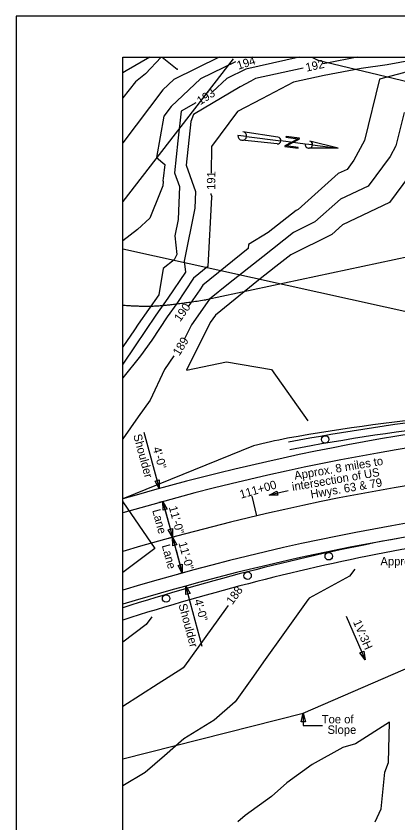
# Model space of a CAD drawing. Extents: x 1385284 to 1385995, y 1975154 to 1975620.
# Drawn here: x 1385283.8 to 1385397.4, y 1975379.9 to 1975619.6 of the extents above; entities that cross this region are included whole.
import ezdxf

# ---------------------------------------------------------------- set-up
doc = ezdxf.new("R2010")
doc.units = 0
for name, color, linetype in [('1', 7, 'Continuous'), ('Default', 7, 'Continuous'), ('DTM CONTOURS_MAJOR', 7, 'Continuous'), ('DTM_CONTOURS_MINOR', 7, 'Continuous'), ('Level 1', 7, 'Continuous'), ('R_Guardrail', 7, 'Continuous'), ('R_Horz Alg', 7, 'Continuous'), ('R_Horz Alg Annot', 7, 'Continuous'), ('R_Horz Alg Stationing', 7, 'Continuous'), ('R_Proposed Const Limits', 7, 'Continuous'), ('R_Proposed Road', 7, 'Continuous'), ('R_Shld', 7, 'Continuous'), ('S_CROSS_DRAIN', 7, 'Continuous'), ('S_DRG_PT_SYM', 7, 'Continuous'), ('S_SHOULDER', 7, 'Continuous'), ('S_UTL_PT_SYM', 7, 'Continuous'), ('S_WATER_UTILITIES', 7, 'Continuous')]:
    doc.layers.add(name, color=color, linetype=linetype)

msp = doc.modelspace()

# ---------------------------------------------------------------- linework, layer by layer
at = {"layer": '1'}
msp.add_line((1385315.54, 1975607.41), (1385982.69, 1975607.41), dxfattribs=at)
for points in [[(1385994.75, 1975619.62), (1385283.84, 1975619.62), (1385283.84, 1975153.74), (1385994.75, 1975153.74)], [(1385315.54, 1975165.95), (1385315.54, 1975607.41), (1385810.69, 1975607.41), (1385810.69, 1975586.48), (1385892.57, 1975586.48), (1385892.57, 1975580.3), (1385982.69, 1975580.3), (1385982.69, 1975165.95)]]:
    msp.add_lwpolyline(points, close=True, dxfattribs=at)
at = {"layer": 'Default'}
for p, q in [((1385321.87, 1975496.01), (1385326.44, 1975479.22)), ((1385325.23, 1975478.89), (1385325.23, 1975478.89)), ((1385364.76, 1975478.59), (1385359.11, 1975477.29)), ((1385328.05, 1975475.52), (1385326.28, 1975475.04)), ((1385327.49, 1975475.36), (1385330.37, 1975464.75)), ((1385329.32, 1975468.61), (1385327.49, 1975475.36)), ((1385326.28, 1975475.03), (1385326.28, 1975475.03)), ((1385330.94, 1975464.9), (1385329.17, 1975464.42)), ((1385330.37, 1975464.75), (1385333.26, 1975454.13)), ((1385331.42, 1975460.89), (1385333.26, 1975454.13)), ((1385333.82, 1975454.29), (1385332.05, 1975453.81)), ((1385332.05, 1975453.8), (1385332.05, 1975453.8)), ((1385333.1, 1975449.94), (1385333.1, 1975449.94)), ((1385339.2, 1975432.28), (1385334.31, 1975450.27)), ((1385382.05, 1975441.26), (1385387.65, 1975428.32)), ((1385369.26, 1975412.44), (1385369.26, 1975408.85)), ((1385369.26, 1975408.85), (1385374.94, 1975408.85))]:
    msp.add_line(p, q, dxfattribs=at)
for points in [[(1385326.38, 1975481.8), (1385326.44, 1975479.22), (1385325.18, 1975481.47)], [(1385361.69, 1975477.24), (1385359.11, 1975477.29), (1385361.41, 1975478.46)], [(1385327.54, 1975472.79), (1385327.49, 1975475.36), (1385328.75, 1975473.12)], [(1385327.54, 1975472.78), (1385327.49, 1975475.36), (1385328.75, 1975473.11)], [(1385330.32, 1975467.33), (1385330.37, 1975464.75), (1385329.11, 1975467)], [(1385330.42, 1975462.17), (1385330.37, 1975464.75), (1385331.63, 1975462.5)], [(1385333.21, 1975456.71), (1385333.26, 1975454.13), (1385332, 1975456.38)], [(1385333.21, 1975456.71), (1385333.26, 1975454.13), (1385332, 1975456.38)], [(1385334.36, 1975447.7), (1385334.31, 1975450.27), (1385335.57, 1975448.02)], [(1385387.23, 1975430.86), (1385387.65, 1975428.32), (1385386.08, 1975430.36)], [(1385368.63, 1975409.94), (1385369.26, 1975412.44), (1385369.88, 1975409.94)]]:
    msp.add_lwpolyline(points, close=True, dxfattribs=at)
at = {"layer": 'DTM CONTOURS_MAJOR'}
for points in [[(1385344.28, 1975607.41), (1385330.72, 1975600.78), (1385327.45, 1975597.68), (1385315.54, 1975581.97)], [(1385399.62, 1975602.92), (1385399.04, 1975602.82), (1385391.96, 1975600.88), (1385387.45, 1975582.67), (1385384.31, 1975576.79), (1385382.28, 1975574.04), (1385379.69, 1975572.81), (1385367.75, 1975562.2), (1385367.14, 1975561.9), (1385358.79, 1975555.31), (1385352.95, 1975551.79), (1385352.89, 1975550.54), (1385339.43, 1975539.66), (1385338.49, 1975538.24), (1385335.03, 1975533.36)], [(1385315.54, 1975475.27), (1385325.14, 1975461.45), (1385315.54, 1975454.26)]]:
    msp.add_lwpolyline(points, dxfattribs=at)
at = {"layer": 'DTM_CONTOURS_MINOR'}
for points in [[(1385327.01, 1975607.41), (1385322.31, 1975602.51), (1385319.36, 1975600.08), (1385315.54, 1975595.3)], [(1385368.04, 1975607.41), (1385352.21, 1975603.89), (1385346.56, 1975601.12), (1385342.3, 1975597.1)], [(1385385.31, 1975607.41), (1385376.24, 1975605.69), (1385375.12, 1975605.45)], [(1385349.07, 1975606.05), (1385338.64, 1975600.95), (1385330.01, 1975592.78), (1385327.83, 1975589.91), (1385325.56, 1975577.58), (1385328.04, 1975575.57), (1385327.55, 1975571.35), (1385327.49, 1975570.73), (1385327.58, 1975570.47), (1385327.53, 1975569.17), (1385326.67, 1975567.25), (1385323.63, 1975559.56), (1385319.95, 1975556.23), (1385315.54, 1975552.86)], [(1385514.59, 1975561.54), (1385512.54, 1975562.62), (1385501.11, 1975567.56), (1385496.85, 1975570), (1385485.37, 1975578.7), (1385479.84, 1975581.7), (1385469.1, 1975589.65), (1385457.89, 1975594.57), (1385449.84, 1975598.03), (1385440.13, 1975602.29), (1385428.54, 1975605.71), (1385423.05, 1975606.12), (1385417.26, 1975606.55), (1385404.45, 1975607), (1385394.25, 1975605.12), (1385386.47, 1975604.03), (1385375.43, 1975601.95), (1385366.35, 1975599.96), (1385356.91, 1975595.01), (1385349.74, 1975591.25), (1385341.99, 1975580.91), (1385341.88, 1975572.91)], [(1385369.26, 1975604.16), (1385355.09, 1975601.06), (1385353.62, 1975600.29), (1385350.48, 1975598.64), (1385336.6, 1975590.39), (1385335.78, 1975588.28), (1385334.46, 1975575.29), (1385337.21, 1975567.51), (1385337.02, 1975562.57), (1385333.86, 1975546.8), (1385334.18, 1975543.53), (1385328.93, 1975535.79), (1385325.43, 1975530.76), (1385319.28, 1975521.64), (1385315.54, 1975516.24)], [(1385337.27, 1975593.88), (1385332.96, 1975591.37), (1385331.95, 1975582.54), (1385330.97, 1975573.01), (1385332.4, 1975568.99), (1385332.02, 1975559.15), (1385331.06, 1975554.36), (1385331.61, 1975548.75), (1385330.89, 1975547.15), (1385327.6, 1975544.63), (1385326.26, 1975536.84), (1385320.18, 1975528.09), (1385319.01, 1975526.36), (1385315.54, 1975521.35)], [(1385399.23, 1975591.02), (1385396.78, 1975581.11), (1385395.07, 1975577.92), (1385388.6, 1975569.12), (1385380.31, 1975565.21), (1385372.74, 1975558.48), (1385366.36, 1975555.31), (1385357.23, 1975548.12), (1385346.99, 1975540.04), (1385341.41, 1975535.54), (1385335.97, 1975527.87), (1385333.9, 1975523.73)], [(1385402.83, 1975574.97), (1385394.91, 1975564.2), (1385380.94, 1975557.61), (1385377.74, 1975554.77), (1385365.57, 1975548.73), (1385361.06, 1975545.17), (1385355.99, 1975541.17), (1385343.15, 1975530.79), (1385341.61, 1975528.62), (1385334.49, 1975514.44), (1385346.45, 1975516.91), (1385359.8, 1975514.64), (1385370.64, 1975499.32)], [(1385341.8, 1975566.91), (1385341.79, 1975566.68), (1385342.03, 1975566.02), (1385342.03, 1975566), (1385341.99, 1975565.82), (1385340.91, 1975545.21), (1385336.65, 1975541.76), (1385331.68, 1975534.26), (1385328.81, 1975530.22), (1385324.2, 1975523.32), (1385320.87, 1975518.63), (1385315.54, 1975512.1)], [(1385330.78, 1975518.63), (1385327.94, 1975514.62), (1385323.7, 1975505.5), (1385320.15, 1975500.5), (1385315.54, 1975494)], [(1385384.61, 1975455.29), (1385383.06, 1975453.21), (1385371, 1975446.69), (1385370.71, 1975446.29), (1385370.59, 1975446.12), (1385363.19, 1975435.73), (1385357.96, 1975428.4), (1385353.91, 1975422.75), (1385348.97, 1975415.84), (1385342.72, 1975410.39), (1385333.74, 1975404.82), (1385328, 1975399.83), (1385322.27, 1975394.83), (1385315.54, 1975390.88)], [(1385346.83, 1975444.43), (1385346.81, 1975444.4), (1385346.1, 1975443.41), (1385333.91, 1975426.45), (1385333.58, 1975425.99), (1385333.17, 1975425.63), (1385326.07, 1975421.23), (1385315.54, 1975414.45)], [(1385324.2, 1975441.14), (1385322.56, 1975438.81), (1385315.54, 1975433.55)], [(1385390.67, 1975380.2), (1385392.4, 1975384.09), (1385393.51, 1975394.98), (1385394.58, 1975397.83), (1385394.96, 1975409.79), (1385384.78, 1975403.37), (1385381.07, 1975402.27), (1385371.89, 1975397.26), (1385364.39, 1975391.78), (1385359.79, 1975387.75), (1385352.01, 1975382.09), (1385349.84, 1975380.2)]]:
    msp.add_lwpolyline(points, dxfattribs=at)
at = {"layer": 'Level 1'}
for p, q in [((1385352.4, 1975583.84), (1385349.83, 1975584.17)), ((1385349.83, 1975584.17), (1385349.83, 1975584.17)), ((1385361.72, 1975583.64), (1385351.32, 1975585.28)), ((1385352.4, 1975583.84), (1385362.57, 1975582.54)), ((1385364.14, 1975583.86), (1385364.11, 1975583.61)), ((1385368.07, 1975583.1), (1385368.11, 1975583.35)), ((1385361.47, 1975581.68), (1385350.99, 1975582.72)), ((1385369.84, 1975581.61), (1385362.57, 1975582.54)), ((1385363.79, 1975581.11), (1385363.75, 1975580.86)), ((1385371.98, 1975581.33), (1385369.84, 1975581.61)), ((1385369.84, 1975581.61), (1385369.84, 1975581.59)), ((1385379.66, 1975580.35), (1385371.17, 1975582.5)), ((1385371.98, 1975581.33), (1385379.66, 1975580.35)), ((1385367.72, 1975580.35), (1385367.75, 1975580.6)), ((1385379.66, 1975580.35), (1385370.9, 1975580.38))]:
    msp.add_line(p, q, dxfattribs=at)
for points in [[(1385367.71, 1975583.15), (1385363.79, 1975581.11)], [(1385364.11, 1975583.61), (1385367.71, 1975583.15)], [(1385368.11, 1975583.35), (1385364.14, 1975583.86)], [(1385364.15, 1975581.07), (1385368.07, 1975583.1)], [(1385363.75, 1975580.86), (1385367.72, 1975580.35)], [(1385367.75, 1975580.6), (1385364.15, 1975581.07)]]:
    msp.add_lwpolyline(points, dxfattribs=at)
for centre, radius, start, end in [((1385351.11, 1975584), 1.29, 172.7064, 352.7064), ((1385351.11, 1975584), 1.29, 352.7064, 81.0414), ((1385361.6, 1975582.66), 0.984, 352.7034, 82.777), ((1385361.6, 1975582.66), 0.984, 262.777, 352.7034), ((1385370.91, 1975581.46), 1.08, 173.0609, 353.2831), ((1385370.91, 1975581.46), 1.08, 353.2831, 75.7678)]:
    msp.add_arc(centre, radius, start, end, dxfattribs=at)
at = {"layer": 'R_Guardrail'}
for centre in [(1385375.79, 1975493.83), (1385376.84, 1975459.11), (1385352.69, 1975453.34), (1385328.45, 1975446.56)]:
    msp.add_circle(centre, 1.11, dxfattribs=at)
for centre, radius, start, end in [((1385496.71, 1974793.55), 711.77, 96.54062, 100.67501), ((1385496.71, 1974793.55), 709.49, 96.54062, 100.67501), ((1385515.91, 1974795.32), 679.49, 96.60918, 100.21868), ((1385522.21, 1974796.51), 679.47, 100.75858, 107.70744)]:
    msp.add_arc(centre, radius, start, end, dxfattribs=at)
at = {"layer": 'R_Horz Alg'}
msp.add_arc((1385514.36, 1974795.07), 694.49, 77.49826, 106.63511, dxfattribs=at)
at = {"layer": 'R_Horz Alg Annot'}
for p, q in [((1385348.44, 1975606.95), (1385315.54, 1975564.49)), ((1385315.54, 1975550.51), (1385664.69, 1975473.09))]:
    msp.add_line(p, q, dxfattribs=at)
at = {"layer": 'R_Horz Alg Stationing'}
msp.add_line((1385355.46, 1975471.14), (1385354.09, 1975476.98), dxfattribs=at)
at = {"layer": 'R_Proposed Const Limits'}
for points in [[(1385461.53, 1975561.1), (1385340.37, 1975535.35)], [(1385315.54, 1975398.93), (1385369.26, 1975412.44), (1385438.34, 1975442.35)]]:
    msp.add_lwpolyline(points, dxfattribs=at)
msp.add_open_spline([(1385315.54, 1975533.74), (1385321.69, 1975533.28), (1385329.85, 1975533.76), (1385340.37, 1975535.35)], degree=2, dxfattribs=at)
at = {"layer": 'R_Proposed Road'}
for radius, end in [(705.49, 106.36838), (683.49, 106.91082)]:
    msp.add_arc((1385514.36, 1974795.07), radius, 77.49826, end, dxfattribs=at)
at = {"layer": 'R_Shld'}
msp.add_line((1385354.45, 1975491.95), (1385315.54, 1975476.17), dxfattribs=at)
for centre, radius, start, end in [((1385514.36, 1974795.07), 709.49, 93.55435, 106.27353), ((1385487.08, 1974789.91), 714.86, 95.74275, 99.87127), ((1385514.67, 1974793.6), 716.49, 102.09645, 102.92145), ((1385514.36, 1974795.07), 679.49, 96.47637, 107.01339), ((1385514.36, 1974795.07), 675.99, 96.48073, 100.08496), ((1385522.32, 1974796.3), 676.22, 100.76753, 107.80548)]:
    msp.add_arc(centre, radius, start, end, dxfattribs=at)
at = {"layer": 'S_CROSS_DRAIN'}
msp.add_line((1385327.29, 1975607.41), (1385331.78, 1975603.86), dxfattribs=at)
at = {"layer": 'S_DRG_PT_SYM'}
msp.add_lwpolyline([(1385331.78, 1975603.86), (1385331.83, 1975603.85), (1385331.78, 1975603.86), (1385331.79, 1975603.91), (1385331.78, 1975603.86), (1385331.73, 1975603.87), (1385331.78, 1975603.86), (1385331.77, 1975603.81)], dxfattribs=at)
at = {"layer": 'S_SHOULDER'}
msp.add_lwpolyline([(1385323.65, 1975607.41), (1385316.54, 1975603.41), (1385315.54, 1975602.79)], dxfattribs=at)
at = {"layer": 'S_UTL_PT_SYM'}
msp.add_lwpolyline([(1385373.63, 1975606.53), (1385373.68, 1975606.52), (1385373.63, 1975606.53), (1385373.64, 1975606.57), (1385373.63, 1975606.53), (1385373.58, 1975606.54), (1385373.63, 1975606.53), (1385373.62, 1975606.48)], dxfattribs=at)
at = {"layer": 'S_WATER_UTILITIES'}
for p, q in [((1385371.84, 1975607.41), (1385373.63, 1975606.53)), ((1385373.63, 1975606.53), (1385516.1, 1975572.28))]:
    msp.add_line(p, q, dxfattribs=at)

# ---------------------------------------------------------------- texts
at = {"layer": 'Default'}
for s, rotation, p in [('194', 17.9559, (1385349.97, 1975603.68)), ('192', 12.3483, (1385370.24, 1975603.1)), ('193', 32.5894, (1385338.62, 1975593.11)), ('191', 89.2259, (1385343.06, 1975567.95)), ('190', 54.5302, (1385332.64, 1975528.63)), ('189', 58.6305, (1385332.4, 1975518.48)), ('Shoulder', 285.2191, (1385318.66, 1975495.07)), ('4\'-0"', 285.2191, (1385324.46, 1975491.26)), ('Approx. 8 miles to', 9.6733, (1385366.78, 1975481.82)), ('intersection of US', 9.6733, (1385366.1, 1975478.52)), ('111+00', 16.2079, (1385350.73, 1975476.2)), ('Hwys. 63 & 79', 9.6733, (1385371.63, 1975476.29)), ('Lane', 285.2105, (1385324.31, 1975472.73)), ('11\'-0"', 285.2105, (1385329.24, 1975473.69)), ('11\'-0"', 285.2105, (1385332.12, 1975463.07)), ('Lane', 285.2105, (1385327.15, 1975462.28)), ('188', 54.353, (1385348.18, 1975444.54)), ('Shoulder', 285.2191, (1385332.12, 1975444.7)), ('4\'-0"', 285.2017, (1385336.76, 1975446)), ('1V:3H', 293.4104, (1385384.01, 1975439.59))]:
    msp.add_text(s, height=2.5, rotation=rotation, dxfattribs=at).set_placement(p)
for s, p in [('Approach Slab', (1385392.2, 1975456.38)), ('Toe of ', (1385374.74, 1975409.44)), ('Slope', (1385376.48, 1975406.31))]:
    msp.add_text(s, height=2.5, dxfattribs=at).set_placement(p)

doc.saveas('drawing.dxf')
